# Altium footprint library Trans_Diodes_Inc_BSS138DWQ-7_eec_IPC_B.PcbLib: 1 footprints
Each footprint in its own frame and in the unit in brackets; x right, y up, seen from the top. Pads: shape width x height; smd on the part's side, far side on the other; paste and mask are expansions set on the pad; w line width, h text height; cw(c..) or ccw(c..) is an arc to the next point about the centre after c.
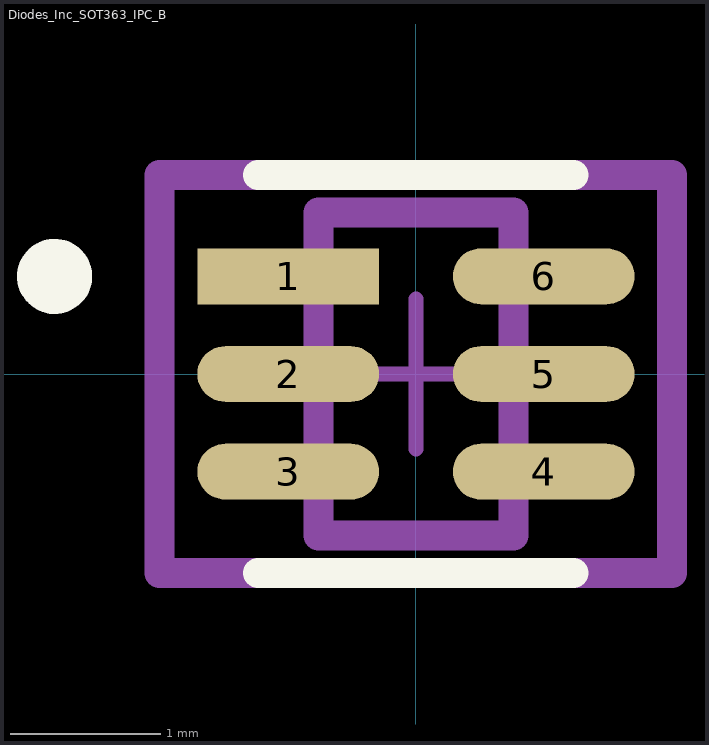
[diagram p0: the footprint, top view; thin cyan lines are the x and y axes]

## Diodes_Inc_SOT363_IPC_B [mil]
pads (6):
  rect 47.65x14.65 smd paste+0 mask+0: 1(-33.5,25.59)
  rrect100% 47.65x14.65 smd paste+0 mask+0: 2(-33.5,0) 3(-33.5,-25.59) 4(33.5,-25.59) 5(33.5,0) 6(33.5,25.59)
Top Overlay:
  circle w9.84: c-94.73,25.59 r4.92
  lines w7.87: -41.34,-52.17 41.34,-52.17 ; -41.34,52.17 41.34,52.17
Mechanical 10:
  lines w7.87: -67.17,-52.17 67.17,-52.17 67.17,52.17 -67.17,52.17 -67.17,-52.17
  text ".Designator" at 0,7.41 h39.37
Mechanical 12:
  lines w7.87: -25.59,-42.32 25.59,-42.32 25.59,42.32 -25.59,42.32 -25.59,-42.32
Mechanical 15:
  lines w3.94: -19.68,0 19.68,0 ; 0,-19.68 0,19.68
  lines w7.87: -67.17,-52.17 67.17,-52.17 67.17,52.17 -67.17,52.17 -67.17,-52.17
3D body "Trans_Diodes_Inc_BSS138DWQ-7_eec.STEP": height 10, standoff 0, extent -67.17,-52.17 67.17,52.17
